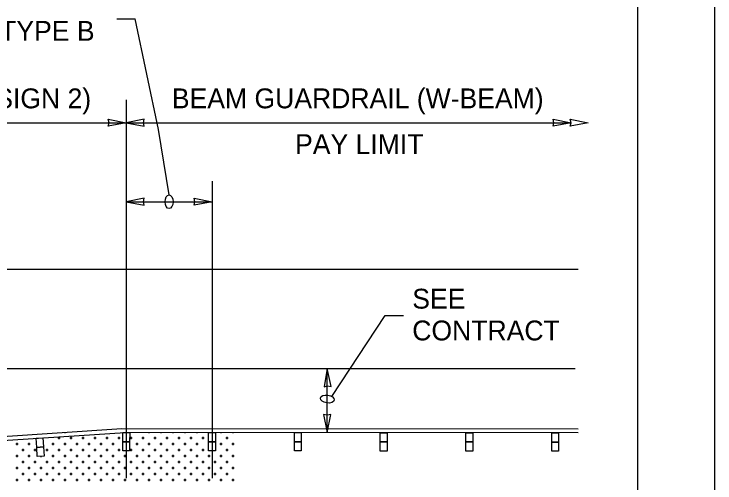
# Model space of a CAD drawing. Extents: x 1312564.5 to 1312581.5, y 1207298.4 to 1207309.4.
# Drawn here: x 1312578.654 to 1312581.478, y 1207305.142 to 1207307.031 of the extents above; entities that cross this region are included whole.
import ezdxf

# ---------------------------------------------------------------- set-up
doc = ezdxf.new("R2010")
doc.units = 0
for name, color, linetype in [('Level 15', 7, 'Continuous'), ('Level 2', 7, 'Continuous'), ('Level 20', 7, 'Continuous'), ('Level 21', 7, 'Continuous'), ('Level 3', 7, 'Continuous'), ('Level 4', 7, 'Continuous'), ('Level 44', 7, 'Continuous'), ('SH_GI_PlotLimits', 7, 'Continuous'), ('SH_GI_SheetBorder', 7, 'Continuous')]:
    doc.layers.add(name, color=color, linetype=linetype)

msp = doc.modelspace()

# ---------------------------------------------------------------- linework, layer by layer
at = {"layer": 'Level 15'}
for p, q in [((1312579.0686, 1207307.0115), (1312579.1423, 1207307.0115)), ((1312579.2362, 1207306.5653), (1312579.1423, 1207307.0115)), ((1312579.106, 1207306.5929), (1312580.898, 1207306.5929)), ((1312579.2788, 1207306.3023), (1312579.2362, 1207306.5653)), ((1312579.106, 1207306.2746), (1312579.4516, 1207306.2746)), ((1312580.1493, 1207305.8171), (1312580.2229, 1207305.8171)), ((1312579.9152, 1207305.3458), (1312579.9158, 1207305.6025))]:
    msp.add_line(p, q, dxfattribs=at)
for points in [[(1312579.106, 1207306.685), (1312579.106, 1207305.1613)], [(1312576.1354, 1207306.5929), (1312579.106, 1207306.5929)], [(1312579.4516, 1207306.3572), (1312579.4516, 1207305.1613)]]:
    msp.add_lwpolyline(points, dxfattribs=at)
for points in [[(1312579.106, 1207306.5929), (1312579.0336, 1207306.5787), (1312579.0369, 1207306.5929), (1312579.0336, 1207306.6071)], [(1312579.106, 1207306.5929), (1312579.1785, 1207306.5787), (1312579.1751, 1207306.5929), (1312579.1785, 1207306.6071)], [(1312580.898, 1207306.5929), (1312580.8256, 1207306.5787), (1312580.8289, 1207306.5929), (1312580.8256, 1207306.6071)], [(1312580.9671, 1207306.5929), (1312580.8947, 1207306.5787), (1312580.898, 1207306.5929), (1312580.8947, 1207306.6071)], [(1312579.106, 1207306.2746), (1312579.1785, 1207306.2604), (1312579.1751, 1207306.2746), (1312579.1785, 1207306.2888)], [(1312579.4516, 1207306.2746), (1312579.3792, 1207306.2604), (1312579.3825, 1207306.2746), (1312579.3792, 1207306.2888)], [(1312579.9158, 1207305.6025), (1312579.9028, 1207305.5298), (1312579.917, 1207305.5334), (1312579.9313, 1207305.5303)], [(1312579.9153, 1207305.3456), (1312579.9297, 1207305.418), (1312579.9155, 1207305.4147), (1312579.9013, 1207305.4181)]]:
    msp.add_lwpolyline(points, close=True, dxfattribs=at)
for centre, major_axis in [((1312579.2788, 1207306.2746), (0, -0.0276)), ((1312579.9161, 1207305.4801), (-0.0274, 0.0038))]:
    msp.add_ellipse(centre, major_axis=major_axis, ratio=0.57735, dxfattribs=at)
at = {"layer": 'Level 2'}
for p, q in [((1312579.0887, 1207305.3604), (1312577.009, 1207305.2227)), ((1312580.9266, 1207305.3591), (1312579.0887, 1207305.3604)), ((1312577.01, 1207305.2075), (1312579.1015, 1207305.346)), ((1312580.9265, 1207305.3438), (1312579.1049, 1207305.3452))]:
    msp.add_line(p, q, dxfattribs=at)
for points in [[(1312579.0922, 1207305.3452), (1312579.1199, 1207305.3451), (1312579.1198, 1207305.3083), (1312579.0922, 1207305.3083)], [(1312579.4378, 1207305.3449), (1312579.4655, 1207305.3449), (1312579.4654, 1207305.308), (1312579.4378, 1207305.308)], [(1312579.7834, 1207305.3447), (1312579.8111, 1207305.3446), (1312579.811, 1207305.3078), (1312579.7834, 1207305.3078)], [(1312580.129, 1207305.3444), (1312580.1567, 1207305.3444), (1312580.1566, 1207305.3075), (1312580.129, 1207305.3075)], [(1312580.4746, 1207305.3441), (1312580.5023, 1207305.3441), (1312580.5022, 1207305.3073), (1312580.4746, 1207305.3073)], [(1312580.8202, 1207305.3439), (1312580.8479, 1207305.3439), (1312580.8478, 1207305.307), (1312580.8202, 1207305.307)], [(1312578.7428, 1207305.3222), (1312578.7704, 1207305.3241), (1312578.7728, 1207305.2873), (1312578.7453, 1207305.2855)], [(1312579.0922, 1207305.3083), (1312579.1198, 1207305.3083), (1312579.1198, 1207305.2714), (1312579.0922, 1207305.2714)], [(1312579.4378, 1207305.308), (1312579.4654, 1207305.308), (1312579.4654, 1207305.2712), (1312579.4378, 1207305.2712)], [(1312579.7834, 1207305.3078), (1312579.811, 1207305.3078), (1312579.811, 1207305.2709), (1312579.7834, 1207305.2709)], [(1312580.129, 1207305.3075), (1312580.1566, 1207305.3075), (1312580.1566, 1207305.2707), (1312580.129, 1207305.2707)], [(1312580.4746, 1207305.3073), (1312580.5022, 1207305.3073), (1312580.5022, 1207305.2704), (1312580.4746, 1207305.2704)], [(1312580.8202, 1207305.307), (1312580.8478, 1207305.307), (1312580.8478, 1207305.2701), (1312580.8202, 1207305.2702)], [(1312578.7453, 1207305.2855), (1312578.7728, 1207305.2873), (1312578.7753, 1207305.2505), (1312578.7477, 1207305.2487)]]:
    msp.add_lwpolyline(points, close=True, dxfattribs=at)
at = {"layer": 'Level 21'}
msp.add_line((1312579.9347, 1207305.4903), (1312580.1493, 1207305.8171), dxfattribs=at)
at = {"layer": 'Level 3'}
msp.add_line((1312575.556, 1207305.6025), (1312580.9146, 1207305.6025), dxfattribs=at)
at = {"layer": 'Level 4'}
for p, q in [((1312578.8356, 1207305.3187), (1312578.8356, 1207305.3279)), ((1312578.8597, 1207305.3429), (1312578.8597, 1207305.3453)), ((1312578.8839, 1207305.3187), (1312578.8839, 1207305.3279)), ((1312578.9322, 1207305.3187), (1312578.9322, 1207305.3279)), ((1312578.9805, 1207305.3187), (1312578.9805, 1207305.3279)), ((1312579.0289, 1207305.3187), (1312579.0289, 1207305.3279)), ((1312579.0772, 1207305.3187), (1312579.0772, 1207305.3279)), ((1312579.1255, 1207305.3187), (1312579.1255, 1207305.3279)), ((1312579.1739, 1207305.3187), (1312579.1739, 1207305.3279)), ((1312579.198, 1207305.3429), (1312579.198, 1207305.3451)), ((1312579.2222, 1207305.3187), (1312579.2222, 1207305.3279)), ((1312579.2464, 1207305.3429), (1312579.2464, 1207305.345)), ((1312579.2705, 1207305.3187), (1312579.2705, 1207305.3279)), ((1312579.2947, 1207305.3429), (1312579.2947, 1207305.345)), ((1312579.3188, 1207305.3187), (1312579.3188, 1207305.3279)), ((1312579.343, 1207305.3429), (1312579.343, 1207305.345)), ((1312579.3672, 1207305.3187), (1312579.3672, 1207305.3279)), ((1312579.3913, 1207305.3429), (1312579.3913, 1207305.3449)), ((1312579.4155, 1207305.3187), (1312579.4155, 1207305.3279)), ((1312579.488, 1207305.3429), (1312579.488, 1207305.3449)), ((1312579.5122, 1207305.3187), (1312579.5122, 1207305.3279)), ((1312579.5363, 1207305.3429), (1312579.5363, 1207305.3448)), ((1312578.6618, 1207305.2992), (1312578.671, 1207305.2992)), ((1312578.6664, 1207305.2946), (1312578.6664, 1207305.3038)), ((1312578.7101, 1207305.2992), (1312578.7194, 1207305.2992)), ((1312578.7147, 1207305.2946), (1312578.7147, 1207305.3038)), ((1312578.8068, 1207305.2992), (1312578.816, 1207305.2992)), ((1312578.8114, 1207305.2946), (1312578.8114, 1207305.3038)), ((1312578.831, 1207305.3233), (1312578.8402, 1207305.3233)), ((1312578.8551, 1207305.2992), (1312578.8643, 1207305.2992)), ((1312578.8597, 1207305.2946), (1312578.8597, 1207305.3038)), ((1312578.8793, 1207305.3233), (1312578.8885, 1207305.3233)), ((1312578.9034, 1207305.2992), (1312578.9127, 1207305.2992)), ((1312578.9081, 1207305.2946), (1312578.9081, 1207305.3038)), ((1312578.9276, 1207305.3233), (1312578.9368, 1207305.3233)), ((1312578.9518, 1207305.2992), (1312578.961, 1207305.2992)), ((1312578.9564, 1207305.2946), (1312578.9564, 1207305.3038)), ((1312578.9759, 1207305.3233), (1312578.9852, 1207305.3233)), ((1312579.0001, 1207305.2992), (1312579.0093, 1207305.2992)), ((1312579.0047, 1207305.2946), (1312579.0047, 1207305.3038)), ((1312579.0243, 1207305.3233), (1312579.0335, 1207305.3233)), ((1312579.0484, 1207305.2992), (1312579.053, 1207305.2992)), ((1312579.053, 1207305.2946), (1312579.053, 1207305.3038)), ((1312579.053, 1207305.2992), (1312579.0576, 1207305.2992)), ((1312579.0726, 1207305.3233), (1312579.0818, 1207305.3233)), ((1312579.1209, 1207305.3233), (1312579.1301, 1207305.3233)), ((1312579.1451, 1207305.2992), (1312579.1543, 1207305.2992)), ((1312579.1497, 1207305.2946), (1312579.1497, 1207305.3038)), ((1312579.1693, 1207305.3233), (1312579.1785, 1207305.3233)), ((1312579.1934, 1207305.2992), (1312579.2026, 1207305.2992)), ((1312579.198, 1207305.2946), (1312579.198, 1207305.3038)), ((1312579.2176, 1207305.3233), (1312579.2268, 1207305.3233)), ((1312579.2417, 1207305.2992), (1312579.251, 1207305.2992)), ((1312579.2464, 1207305.2946), (1312579.2464, 1207305.3038)), ((1312579.2659, 1207305.3233), (1312579.2751, 1207305.3233)), ((1312579.2901, 1207305.2992), (1312579.2993, 1207305.2992)), ((1312579.2947, 1207305.2946), (1312579.2947, 1207305.3038)), ((1312579.3142, 1207305.3233), (1312579.3235, 1207305.3233)), ((1312579.3384, 1207305.2992), (1312579.343, 1207305.2992)), ((1312579.343, 1207305.2946), (1312579.343, 1207305.3038)), ((1312579.343, 1207305.2992), (1312579.3476, 1207305.2992)), ((1312579.3626, 1207305.3233), (1312579.3718, 1207305.3233)), ((1312579.3867, 1207305.2992), (1312579.3959, 1207305.2992)), ((1312579.3913, 1207305.2946), (1312579.3913, 1207305.3038)), ((1312579.4109, 1207305.3233), (1312579.4201, 1207305.3233)), ((1312579.4351, 1207305.2992), (1312579.4378, 1207305.2992)), ((1312579.4654, 1207305.3233), (1312579.4684, 1207305.3233)), ((1312579.4834, 1207305.2992), (1312579.4926, 1207305.2992)), ((1312579.488, 1207305.2946), (1312579.488, 1207305.3038)), ((1312579.5075, 1207305.3233), (1312579.5168, 1207305.3233)), ((1312579.5317, 1207305.2992), (1312579.5409, 1207305.2992)), ((1312579.5363, 1207305.2946), (1312579.5363, 1207305.3038)), ((1312578.686, 1207305.275), (1312578.6952, 1207305.275)), ((1312578.6906, 1207305.2704), (1312578.6906, 1207305.2796)), ((1312578.7343, 1207305.275), (1312578.7435, 1207305.275)), ((1312578.7389, 1207305.2704), (1312578.7389, 1207305.2796)), ((1312578.7826, 1207305.275), (1312578.7918, 1207305.275)), ((1312578.7872, 1207305.2704), (1312578.7872, 1207305.2796)), ((1312578.831, 1207305.275), (1312578.8402, 1207305.275)), ((1312578.8356, 1207305.2704), (1312578.8356, 1207305.2796)), ((1312578.8793, 1207305.275), (1312578.8885, 1207305.275)), ((1312578.8839, 1207305.2704), (1312578.8839, 1207305.2796)), ((1312578.9276, 1207305.275), (1312578.9368, 1207305.275)), ((1312578.9322, 1207305.2704), (1312578.9322, 1207305.2796)), ((1312578.9759, 1207305.275), (1312578.9852, 1207305.275)), ((1312578.9805, 1207305.2704), (1312578.9805, 1207305.2796)), ((1312579.0243, 1207305.275), (1312579.0335, 1207305.275)), ((1312579.0289, 1207305.2704), (1312579.0289, 1207305.2796)), ((1312579.0726, 1207305.275), (1312579.0818, 1207305.275)), ((1312579.0772, 1207305.2704), (1312579.0772, 1207305.2796)), ((1312579.1209, 1207305.275), (1312579.1301, 1207305.275)), ((1312579.1255, 1207305.2704), (1312579.1255, 1207305.2796)), ((1312579.1693, 1207305.275), (1312579.1785, 1207305.275)), ((1312579.1739, 1207305.2704), (1312579.1739, 1207305.2796)), ((1312579.2176, 1207305.275), (1312579.2268, 1207305.275)), ((1312579.2222, 1207305.2704), (1312579.2222, 1207305.2796)), ((1312579.2659, 1207305.275), (1312579.2751, 1207305.275)), ((1312579.2705, 1207305.2704), (1312579.2705, 1207305.2796)), ((1312579.3142, 1207305.275), (1312579.3235, 1207305.275)), ((1312579.3188, 1207305.2704), (1312579.3188, 1207305.2796)), ((1312579.3626, 1207305.275), (1312579.3718, 1207305.275)), ((1312579.3672, 1207305.2704), (1312579.3672, 1207305.2796)), ((1312579.4109, 1207305.275), (1312579.4201, 1207305.275)), ((1312579.4155, 1207305.2704), (1312579.4155, 1207305.2796)), ((1312579.4638, 1207305.2704), (1312579.4638, 1207305.2712)), ((1312579.4654, 1207305.275), (1312579.4684, 1207305.275)), ((1312579.5075, 1207305.275), (1312579.5168, 1207305.275)), ((1312579.5122, 1207305.2704), (1312579.5122, 1207305.2796)), ((1312578.6618, 1207305.2508), (1312578.671, 1207305.2508)), ((1312578.6664, 1207305.2508), (1312578.6664, 1207305.2554)), ((1312578.6664, 1207305.2462), (1312578.6664, 1207305.2508)), ((1312578.7101, 1207305.2508), (1312578.7194, 1207305.2508)), ((1312578.7147, 1207305.2508), (1312578.7147, 1207305.2554)), ((1312578.7147, 1207305.2462), (1312578.7147, 1207305.2508)), ((1312578.7631, 1207305.2462), (1312578.7631, 1207305.2497)), ((1312578.8068, 1207305.2508), (1312578.816, 1207305.2508)), ((1312578.8114, 1207305.2508), (1312578.8114, 1207305.2554)), ((1312578.8114, 1207305.2462), (1312578.8114, 1207305.2508)), ((1312578.8551, 1207305.2508), (1312578.8643, 1207305.2508)), ((1312578.8597, 1207305.2508), (1312578.8597, 1207305.2554)), ((1312578.8597, 1207305.2462), (1312578.8597, 1207305.2508)), ((1312578.9034, 1207305.2508), (1312578.9127, 1207305.2508)), ((1312578.9081, 1207305.2508), (1312578.9081, 1207305.2554)), ((1312578.9081, 1207305.2462), (1312578.9081, 1207305.2508)), ((1312578.9518, 1207305.2508), (1312578.961, 1207305.2508)), ((1312578.9564, 1207305.2508), (1312578.9564, 1207305.2554)), ((1312578.9564, 1207305.2462), (1312578.9564, 1207305.2508)), ((1312579.0001, 1207305.2508), (1312579.0093, 1207305.2508)), ((1312579.0047, 1207305.2508), (1312579.0047, 1207305.2554)), ((1312579.0047, 1207305.2462), (1312579.0047, 1207305.2508)), ((1312579.0484, 1207305.2508), (1312579.053, 1207305.2508)), ((1312579.053, 1207305.2508), (1312579.053, 1207305.2554)), ((1312579.053, 1207305.2462), (1312579.053, 1207305.2508)), ((1312579.053, 1207305.2508), (1312579.0576, 1207305.2508)), ((1312579.0968, 1207305.2508), (1312579.106, 1207305.2508)), ((1312579.1014, 1207305.2508), (1312579.1014, 1207305.2554)), ((1312579.1014, 1207305.2462), (1312579.1014, 1207305.2508)), ((1312579.1451, 1207305.2508), (1312579.1543, 1207305.2508)), ((1312579.1497, 1207305.2508), (1312579.1497, 1207305.2554)), ((1312579.1497, 1207305.2462), (1312579.1497, 1207305.2508)), ((1312579.1934, 1207305.2508), (1312579.2026, 1207305.2508)), ((1312579.198, 1207305.2508), (1312579.198, 1207305.2554)), ((1312579.198, 1207305.2462), (1312579.198, 1207305.2508)), ((1312579.2417, 1207305.2508), (1312579.251, 1207305.2508)), ((1312579.2464, 1207305.2508), (1312579.2464, 1207305.2554)), ((1312579.2464, 1207305.2462), (1312579.2464, 1207305.2508)), ((1312579.2901, 1207305.2508), (1312579.2993, 1207305.2508)), ((1312579.2947, 1207305.2508), (1312579.2947, 1207305.2554)), ((1312579.2947, 1207305.2462), (1312579.2947, 1207305.2508)), ((1312579.3384, 1207305.2508), (1312579.343, 1207305.2508)), ((1312579.343, 1207305.2508), (1312579.343, 1207305.2554)), ((1312579.343, 1207305.2462), (1312579.343, 1207305.2508)), ((1312579.343, 1207305.2508), (1312579.3476, 1207305.2508)), ((1312579.3867, 1207305.2508), (1312579.3959, 1207305.2508)), ((1312579.3913, 1207305.2508), (1312579.3913, 1207305.2554)), ((1312579.3913, 1207305.2462), (1312579.3913, 1207305.2508)), ((1312579.4351, 1207305.2508), (1312579.4443, 1207305.2508)), ((1312579.4397, 1207305.2508), (1312579.4397, 1207305.2554)), ((1312579.4397, 1207305.2462), (1312579.4397, 1207305.2508)), ((1312579.4834, 1207305.2508), (1312579.4926, 1207305.2508)), ((1312579.488, 1207305.2508), (1312579.488, 1207305.2554)), ((1312579.488, 1207305.2462), (1312579.488, 1207305.2508)), ((1312579.5317, 1207305.2508), (1312579.5409, 1207305.2508)), ((1312579.5363, 1207305.2508), (1312579.5363, 1207305.2554)), ((1312579.5363, 1207305.2462), (1312579.5363, 1207305.2508)), ((1312578.686, 1207305.2267), (1312578.6952, 1207305.2267)), ((1312578.6906, 1207305.2221), (1312578.6906, 1207305.2313)), ((1312578.7343, 1207305.2267), (1312578.7435, 1207305.2267)), ((1312578.7389, 1207305.2221), (1312578.7389, 1207305.2313)), ((1312578.7826, 1207305.2267), (1312578.7918, 1207305.2267)), ((1312578.7872, 1207305.2221), (1312578.7872, 1207305.2313)), ((1312578.831, 1207305.2267), (1312578.8402, 1207305.2267)), ((1312578.8356, 1207305.2221), (1312578.8356, 1207305.2313)), ((1312578.8793, 1207305.2267), (1312578.8885, 1207305.2267)), ((1312578.8839, 1207305.2221), (1312578.8839, 1207305.2313)), ((1312578.9276, 1207305.2267), (1312578.9368, 1207305.2267)), ((1312578.9322, 1207305.2221), (1312578.9322, 1207305.2313)), ((1312578.9759, 1207305.2267), (1312578.9852, 1207305.2267)), ((1312578.9805, 1207305.2221), (1312578.9805, 1207305.2313)), ((1312579.0243, 1207305.2267), (1312579.0335, 1207305.2267)), ((1312579.0289, 1207305.2221), (1312579.0289, 1207305.2313)), ((1312579.0726, 1207305.2267), (1312579.0818, 1207305.2267)), ((1312579.0772, 1207305.2221), (1312579.0772, 1207305.2313)), ((1312579.1209, 1207305.2267), (1312579.1301, 1207305.2267)), ((1312579.1255, 1207305.2221), (1312579.1255, 1207305.2313)), ((1312579.1693, 1207305.2267), (1312579.1785, 1207305.2267)), ((1312579.1739, 1207305.2221), (1312579.1739, 1207305.2313)), ((1312579.2176, 1207305.2267), (1312579.2268, 1207305.2267)), ((1312579.2222, 1207305.2221), (1312579.2222, 1207305.2313)), ((1312579.2659, 1207305.2267), (1312579.2751, 1207305.2267)), ((1312579.2705, 1207305.2221), (1312579.2705, 1207305.2313)), ((1312579.3142, 1207305.2267), (1312579.3235, 1207305.2267)), ((1312579.3188, 1207305.2221), (1312579.3188, 1207305.2313)), ((1312579.3626, 1207305.2267), (1312579.3718, 1207305.2267)), ((1312579.3672, 1207305.2221), (1312579.3672, 1207305.2313)), ((1312579.4109, 1207305.2267), (1312579.4201, 1207305.2267)), ((1312579.4155, 1207305.2221), (1312579.4155, 1207305.2313)), ((1312579.4592, 1207305.2267), (1312579.4684, 1207305.2267)), ((1312579.4638, 1207305.2221), (1312579.4638, 1207305.2313)), ((1312579.5075, 1207305.2267), (1312579.5168, 1207305.2267)), ((1312579.5122, 1207305.2221), (1312579.5122, 1207305.2313)), ((1312578.6618, 1207305.2025), (1312578.671, 1207305.2025)), ((1312578.6664, 1207305.1979), (1312578.6664, 1207305.2071)), ((1312578.7101, 1207305.2025), (1312578.7194, 1207305.2025)), ((1312578.7147, 1207305.1979), (1312578.7147, 1207305.2071)), ((1312578.7585, 1207305.2025), (1312578.7631, 1207305.2025)), ((1312578.7631, 1207305.1979), (1312578.7631, 1207305.2071)), ((1312578.7631, 1207305.2025), (1312578.7677, 1207305.2025)), ((1312578.8068, 1207305.2025), (1312578.816, 1207305.2025)), ((1312578.8114, 1207305.1979), (1312578.8114, 1207305.2071)), ((1312578.8551, 1207305.2025), (1312578.8643, 1207305.2025)), ((1312578.8597, 1207305.1979), (1312578.8597, 1207305.2071)), ((1312578.9034, 1207305.2025), (1312578.9127, 1207305.2025)), ((1312578.9081, 1207305.1979), (1312578.9081, 1207305.2071)), ((1312578.9518, 1207305.2025), (1312578.961, 1207305.2025)), ((1312578.9564, 1207305.1979), (1312578.9564, 1207305.2071)), ((1312579.0001, 1207305.2025), (1312579.0093, 1207305.2025)), ((1312579.0047, 1207305.1979), (1312579.0047, 1207305.2071)), ((1312579.0484, 1207305.2025), (1312579.053, 1207305.2025)), ((1312579.053, 1207305.1979), (1312579.053, 1207305.2071)), ((1312579.053, 1207305.2025), (1312579.0576, 1207305.2025)), ((1312579.0968, 1207305.2025), (1312579.106, 1207305.2025)), ((1312579.1014, 1207305.1979), (1312579.1014, 1207305.2071)), ((1312579.1451, 1207305.2025), (1312579.1543, 1207305.2025)), ((1312579.1497, 1207305.1979), (1312579.1497, 1207305.2071)), ((1312579.1934, 1207305.2025), (1312579.2026, 1207305.2025)), ((1312579.198, 1207305.1979), (1312579.198, 1207305.2071)), ((1312579.2417, 1207305.2025), (1312579.251, 1207305.2025)), ((1312579.2464, 1207305.1979), (1312579.2464, 1207305.2071)), ((1312579.2901, 1207305.2025), (1312579.2993, 1207305.2025)), ((1312579.2947, 1207305.1979), (1312579.2947, 1207305.2071)), ((1312579.3384, 1207305.2025), (1312579.343, 1207305.2025)), ((1312579.343, 1207305.1979), (1312579.343, 1207305.2071)), ((1312579.343, 1207305.2025), (1312579.3476, 1207305.2025)), ((1312579.3867, 1207305.2025), (1312579.3959, 1207305.2025)), ((1312579.3913, 1207305.1979), (1312579.3913, 1207305.2071)), ((1312579.4351, 1207305.2025), (1312579.4443, 1207305.2025)), ((1312579.4397, 1207305.1979), (1312579.4397, 1207305.2071)), ((1312579.4834, 1207305.2025), (1312579.4926, 1207305.2025)), ((1312579.488, 1207305.1979), (1312579.488, 1207305.2071)), ((1312579.5317, 1207305.2025), (1312579.5409, 1207305.2025)), ((1312579.5363, 1207305.1979), (1312579.5363, 1207305.2071)), ((1312578.6664, 1207305.1496), (1312578.6664, 1207305.1588)), ((1312578.686, 1207305.1783), (1312578.6952, 1207305.1783)), ((1312578.6906, 1207305.1737), (1312578.6906, 1207305.183)), ((1312578.7147, 1207305.1496), (1312578.7147, 1207305.1588)), ((1312578.7343, 1207305.1783), (1312578.7435, 1207305.1783)), ((1312578.7389, 1207305.1737), (1312578.7389, 1207305.183)), ((1312578.7631, 1207305.1496), (1312578.7631, 1207305.1588)), ((1312578.7826, 1207305.1783), (1312578.7918, 1207305.1783)), ((1312578.7872, 1207305.1737), (1312578.7872, 1207305.183)), ((1312578.8114, 1207305.1496), (1312578.8114, 1207305.1588)), ((1312578.831, 1207305.1783), (1312578.8402, 1207305.1783)), ((1312578.8356, 1207305.1737), (1312578.8356, 1207305.183)), ((1312578.8597, 1207305.1496), (1312578.8597, 1207305.1588)), ((1312578.8793, 1207305.1783), (1312578.8885, 1207305.1783)), ((1312578.8839, 1207305.1737), (1312578.8839, 1207305.183)), ((1312578.9081, 1207305.1496), (1312578.9081, 1207305.1588)), ((1312578.9276, 1207305.1783), (1312578.9368, 1207305.1783)), ((1312578.9322, 1207305.1737), (1312578.9322, 1207305.183)), ((1312578.9564, 1207305.1496), (1312578.9564, 1207305.1588)), ((1312578.9759, 1207305.1783), (1312578.9852, 1207305.1783)), ((1312578.9805, 1207305.1737), (1312578.9805, 1207305.183)), ((1312579.0047, 1207305.1496), (1312579.0047, 1207305.1588)), ((1312579.0243, 1207305.1783), (1312579.0335, 1207305.1783)), ((1312579.0289, 1207305.1737), (1312579.0289, 1207305.183)), ((1312579.053, 1207305.1496), (1312579.053, 1207305.1588)), ((1312579.0726, 1207305.1783), (1312579.0818, 1207305.1783)), ((1312579.0772, 1207305.1737), (1312579.0772, 1207305.183)), ((1312579.1014, 1207305.1496), (1312579.1014, 1207305.1588)), ((1312579.1209, 1207305.1783), (1312579.1301, 1207305.1783)), ((1312579.1255, 1207305.1737), (1312579.1255, 1207305.183)), ((1312579.1497, 1207305.1496), (1312579.1497, 1207305.1588)), ((1312579.1693, 1207305.1783), (1312579.1785, 1207305.1783)), ((1312579.1739, 1207305.1737), (1312579.1739, 1207305.183)), ((1312579.198, 1207305.1496), (1312579.198, 1207305.1588)), ((1312579.2176, 1207305.1783), (1312579.2268, 1207305.1783)), ((1312579.2222, 1207305.1737), (1312579.2222, 1207305.183)), ((1312579.2464, 1207305.1496), (1312579.2464, 1207305.1588)), ((1312579.2659, 1207305.1783), (1312579.2751, 1207305.1783)), ((1312579.2705, 1207305.1737), (1312579.2705, 1207305.183)), ((1312579.2947, 1207305.1496), (1312579.2947, 1207305.1588)), ((1312579.3142, 1207305.1783), (1312579.3235, 1207305.1783)), ((1312579.3188, 1207305.1737), (1312579.3188, 1207305.183)), ((1312579.343, 1207305.1496), (1312579.343, 1207305.1588)), ((1312579.3626, 1207305.1783), (1312579.3718, 1207305.1783)), ((1312579.3672, 1207305.1737), (1312579.3672, 1207305.183)), ((1312579.3913, 1207305.1496), (1312579.3913, 1207305.1588)), ((1312579.4109, 1207305.1783), (1312579.4201, 1207305.1783)), ((1312579.4155, 1207305.1737), (1312579.4155, 1207305.183)), ((1312579.4397, 1207305.1496), (1312579.4397, 1207305.1588)), ((1312579.4592, 1207305.1783), (1312579.4684, 1207305.1783)), ((1312579.4638, 1207305.1737), (1312579.4638, 1207305.183)), ((1312579.488, 1207305.1496), (1312579.488, 1207305.1588)), ((1312579.5075, 1207305.1783), (1312579.5168, 1207305.1783)), ((1312579.5122, 1207305.1737), (1312579.5122, 1207305.183)), ((1312579.5363, 1207305.1496), (1312579.5363, 1207305.1588)), ((1312578.6618, 1207305.1542), (1312578.671, 1207305.1542)), ((1312578.7101, 1207305.1542), (1312578.7194, 1207305.1542)), ((1312578.7585, 1207305.1542), (1312578.7631, 1207305.1542)), ((1312578.7631, 1207305.1542), (1312578.7677, 1207305.1542)), ((1312578.8068, 1207305.1542), (1312578.816, 1207305.1542)), ((1312578.8551, 1207305.1542), (1312578.8643, 1207305.1542)), ((1312578.9034, 1207305.1542), (1312578.9127, 1207305.1542)), ((1312578.9518, 1207305.1542), (1312578.961, 1207305.1542)), ((1312579.0001, 1207305.1542), (1312579.0093, 1207305.1542)), ((1312579.0484, 1207305.1542), (1312579.053, 1207305.1542)), ((1312579.053, 1207305.1542), (1312579.0576, 1207305.1542)), ((1312579.0968, 1207305.1542), (1312579.106, 1207305.1542)), ((1312579.1451, 1207305.1542), (1312579.1543, 1207305.1542)), ((1312579.1934, 1207305.1542), (1312579.2026, 1207305.1542)), ((1312579.2417, 1207305.1542), (1312579.251, 1207305.1542)), ((1312579.2901, 1207305.1542), (1312579.2993, 1207305.1542)), ((1312579.3384, 1207305.1542), (1312579.343, 1207305.1542)), ((1312579.343, 1207305.1542), (1312579.3476, 1207305.1542)), ((1312579.3867, 1207305.1542), (1312579.3959, 1207305.1542)), ((1312579.4351, 1207305.1542), (1312579.4443, 1207305.1542)), ((1312579.4834, 1207305.1542), (1312579.4926, 1207305.1542)), ((1312579.5317, 1207305.1542), (1312579.5409, 1207305.1542))]:
    msp.add_line(p, q, dxfattribs=at)
at = {"layer": 'Level 44'}
msp.add_line((1312575.556, 1207306.0031), (1312580.9267, 1207306.0031), dxfattribs=at)
at = {"layer": 'SH_GI_PlotLimits'}
msp.add_lwpolyline([(1312564.478, 1207298.4209), (1312581.478, 1207298.4209), (1312581.478, 1207309.4209), (1312564.478, 1207309.4209)], close=True, dxfattribs=at)
at = {"layer": 'SH_GI_SheetBorder'}
msp.add_line((1312581.1655, 1207309.1084), (1312581.1655, 1207298.7334), dxfattribs=at)

# ---------------------------------------------------------------- texts
at = {"layer": 'Level 20'}
for s, p in [('BEAM GUARDRAIL BULL NOSE TERMINAL (DESIGN 2)', (1312576.2065, 1207306.6509)), ('BEAM GUARDRAIL (W-BEAM)', (1312579.2898, 1207306.6509)), ('PAY LIMIT', (1312579.7863, 1207306.4666)), ('SEE ', (1312580.2584, 1207305.8442)), ('CONTRACT', (1312580.2584, 1207305.7162))]:
    msp.add_text(s, height=0.08, dxfattribs=at).set_placement(p)
at = {"layer": 'Level 4'}
msp.add_text('REDUCER SECTION TYPE B', height=0.08, dxfattribs=at).set_placement((1312577.5341, 1207306.9227))

doc.saveas('drawing.dxf')
